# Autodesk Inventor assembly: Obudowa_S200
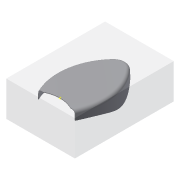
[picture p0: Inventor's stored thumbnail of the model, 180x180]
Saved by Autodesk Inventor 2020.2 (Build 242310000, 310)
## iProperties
Created: 2015-02
Part Number: Obudowa_S200
Document SubType Name: Assembly
Designer: F.Stasiak
Catalog Web Link: www.expertbooks.pl
Manager: www.cadconsulting.pl
Company: Fabian Stasiak CAD Consulting
Author: F.Stasiak
Subject: Zbiór ćwiczeń. Autodesk Inventor 2020. Kurs Professional
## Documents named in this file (3)
- C:\2020_Kurs_Professional\R6 Formy\Obudowa_S200.iam
- C:\2020_Kurs_Professional\R6 Formy\Komponenty\Obudowa_S200_Obudowa_S200_LY.iam
- C:\2020_Kurs_Professional\R6 Formy\Komponenty\Obudowa_S200_RG.ipt
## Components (2 placed, 2 different names)
1. Obudowa_S200_Obudowa_S200_LY:1 [sub-assembly] — Równoległy:1, Równoległy:2, Równoległy:3
2. Obudowa_S200_RG:1
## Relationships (3: Flush 3)
- Równoległy:1 [Flush]: Obudowa_S200_Obudowa_S200_LY:1
- Równoległy:2 [Flush]: Obudowa_S200_Obudowa_S200_LY:1
- Równoległy:3 [Flush]: Obudowa_S200_Obudowa_S200_LY:1
